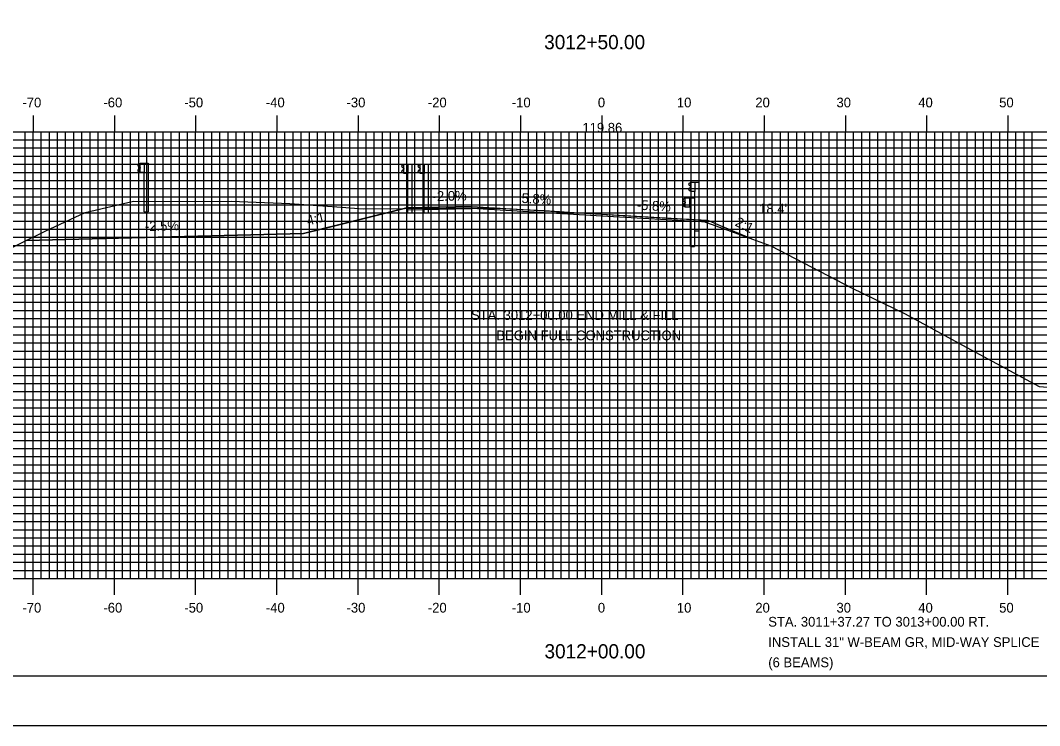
# Model space of a CAD drawing. Extents: x 1684012 to 1684355, y 461260 to 461480.
# Drawn here: x 1684106.1 to 1684231.6, y 461260 to 461346.8 of the extents above; entities that cross this region are included whole.
import ezdxf

# ---------------------------------------------------------------- set-up
doc = ezdxf.new("R2010")
doc.units = 0
for name, color, linetype in [('ANNOTATION', 7, 'Continuous'), ('BORDER', 7, 'Continuous'), ('D_Guardrail_Beam_Rt', 7, 'Continuous'), ('D_Roadway_Centerline', 7, 'Continuous'), ('D_Roadway_Centerline_Text', 7, 'Continuous'), ('D_Roadway_Edge_Shoulder', 7, 'Continuous'), ('D_Roadway_Edge_TW', 7, 'Continuous'), ('D_Roadway_SlopeLines', 7, 'Continuous'), ('D_Text_Standard', 7, 'Continuous'), ('H_V ANNOTATION', 7, 'Continuous'), ('M_Guardrail', 7, 'Continuous'), ('M_Roadway_Centerline', 7, 'Continuous'), ('MAJOR', 7, 'Continuous'), ('MINOR', 7, 'Continuous'), ('PLOT BOUNDARY', 7, 'Continuous'), ('S_Roadway_Centerline', 7, 'Continuous')]:
    doc.layers.add(name, color=color, linetype=linetype)

msp = doc.modelspace()

# ---------------------------------------------------------------- linework, layer by layer
at = {"layer": 'BORDER'}
msp.add_lwpolyline([(1684028.09, 461266.07), (1684348.09, 461266.07), (1684348.09, 461476.07), (1684028.09, 461476.07)], close=True, dxfattribs=at)
at = {"layer": 'D_Guardrail_Beam_Rt'}
for p, q in [((1684187.96, 461324.93), (1684188.65, 461324.93)), ((1684187.96, 461323.77), (1684187.96, 461324.93)), ((1684188.48, 461324.93), (1684188.48, 461323.77)), ((1684188.59, 461324.93), (1684188.59, 461323.77)), ((1684188.65, 461324.93), (1684189.12, 461324.93)), ((1684188.65, 461324.93), (1684188.65, 461323.77)), ((1684189.12, 461324.93), (1684189.12, 461318.93)), ((1684187.87, 461324.83), (1684187.73, 461324.73)), ((1684187.73, 461324.58), (1684187.92, 461324.45)), ((1684187.92, 461324.25), (1684187.73, 461324.11)), ((1684187.73, 461323.97), (1684187.87, 461323.87)), ((1684187.96, 461324.85), (1684187.89, 461324.83)), ((1684187.89, 461323.86), (1684187.96, 461323.85)), ((1684187.96, 461324.38), (1684187.96, 461324.31)), ((1684188.65, 461323.77), (1684187.96, 461323.77)), ((1684188.63, 461318.93), (1684188.63, 461323.77)), ((1684188.63, 461318.93), (1684189.12, 461318.93))]:
    msp.add_line(p, q, dxfattribs=at)
for centre, major_axis, start_param, end_param in [((1684187.78, 461324.66), (-0.0877, 0), 5.323254, 7.243116), ((1684187.78, 461324.04), (-0.0877, 0), 5.323254, 7.243116), ((1684187.89, 461324.79), (-0.0417, 0), 4.907132, 5.323254), ((1684187.89, 461323.9), (-0.0417, 0), 0.959931, 1.376053), ((1684187.88, 461324.38), (0.0789, 0), 0, 0.959931), ((1684187.88, 461324.31), (0.0789, 0), 5.323254, 6.283185)]:
    msp.add_ellipse(centre, major_axis=major_axis, ratio=0.995501, start_param=start_param, end_param=end_param, dxfattribs=at)
at = {"layer": 'D_Roadway_Centerline'}
msp.add_lwpolyline([(1684106.81, 461319.66), (1684140.97, 461320.52), (1684140.99, 461320.52), (1684144.99, 461321.52), (1684144.99, 461321.52), (1684153.68, 461323.7), (1684153.69, 461323.7), (1684161.68, 461323.86), (1684161.69, 461323.86), (1684177.68, 461322.93), (1684177.69, 461322.93), (1684177.7, 461322.93), (1684187.69, 461322.35), (1684190.69, 461322.18), (1684190.69, 461322.17), (1684196.09, 461319.91)], dxfattribs=at)
at = {"layer": 'D_Roadway_Edge_Shoulder'}
for points in [[(1684161.69, 461323.86), (1684153.69, 461323.7), (1684153.69, 461323.45), (1684161.69, 461323.61)], [(1684177.69, 461322.93), (1684187.69, 461322.35), (1684187.69, 461322.35), (1684190.69, 461322.17), (1684190.69, 461321.92), (1684177.69, 461322.68)]]:
    msp.add_lwpolyline(points, close=True, dxfattribs=at)
at = {"layer": 'D_Roadway_Edge_TW'}
msp.add_lwpolyline([(1684161.69, 461323.86), (1684177.69, 461322.93), (1684177.69, 461322.68), (1684161.69, 461323.61)], close=True, dxfattribs=at)
at = {"layer": 'D_Roadway_SlopeLines'}
msp.add_line((1684190.69, 461322.17), (1684196.09, 461319.91), dxfattribs=at)
for points in [[(1684153.69, 461323.7), (1684140.99, 461320.52)], [(1684140.99, 461320.52), (1684106.81, 461319.66)]]:
    msp.add_lwpolyline(points, dxfattribs=at)
at = {"layer": 'M_Guardrail'}
for p, q in [((1684120.76, 461329.11), (1684120.62, 461329.01)), ((1684120.62, 461328.87), (1684120.81, 461328.73)), ((1684120.86, 461329.13), (1684120.78, 461329.12)), ((1684120.85, 461328.66), (1684120.85, 461328.57)), ((1684120.86, 461329.2), (1684121.35, 461329.2)), ((1684120.86, 461328.04), (1684120.86, 461329.2)), ((1684121.35, 461329.2), (1684121.84, 461329.2)), ((1684121.35, 461329.2), (1684121.35, 461328.04)), ((1684121.84, 461329.2), (1684121.84, 461323.2)), ((1684153.24, 461328.99), (1684153.09, 461328.89)), ((1684153.09, 461328.75), (1684153.29, 461328.61)), ((1684153.34, 461329.01), (1684153.25, 461329)), ((1684153.34, 461329.08), (1684153.83, 461329.08)), ((1684153.34, 461327.92), (1684153.34, 461329.08)), ((1684153.83, 461329.08), (1684154.32, 461329.08)), ((1684153.83, 461329.08), (1684153.83, 461327.92)), ((1684154.32, 461329.08), (1684154.32, 461323.08)), ((1684155.24, 461328.99), (1684155.09, 461328.89)), ((1684155.09, 461328.74), (1684155.29, 461328.61)), ((1684155.34, 461329.01), (1684155.26, 461328.99)), ((1684155.34, 461329.08), (1684155.83, 461329.08)), ((1684155.34, 461327.91), (1684155.34, 461329.08)), ((1684155.83, 461329.08), (1684156.32, 461329.08)), ((1684155.83, 461329.08), (1684155.83, 461327.91)), ((1684156.32, 461329.08), (1684156.32, 461323.08)), ((1684120.81, 461328.51), (1684120.62, 461328.37)), ((1684120.62, 461328.23), (1684120.76, 461328.13)), ((1684120.78, 461328.12), (1684120.86, 461328.11)), ((1684121.35, 461328.04), (1684120.86, 461328.04)), ((1684121.35, 461323.2), (1684121.35, 461328.04)), ((1684153.29, 461328.39), (1684153.09, 461328.25)), ((1684153.09, 461328.11), (1684153.24, 461328.01)), ((1684153.25, 461328), (1684153.34, 461327.99)), ((1684153.32, 461328.55), (1684153.32, 461328.45)), ((1684153.83, 461327.92), (1684153.34, 461327.92)), ((1684153.83, 461323.08), (1684153.83, 461327.92)), ((1684155.29, 461328.39), (1684155.09, 461328.25)), ((1684155.09, 461328.11), (1684155.24, 461328.01)), ((1684155.26, 461328), (1684155.34, 461327.99)), ((1684155.32, 461328.54), (1684155.32, 461328.45)), ((1684155.83, 461327.91), (1684155.34, 461327.91)), ((1684155.83, 461323.08), (1684155.83, 461327.91)), ((1684188.56, 461326.79), (1684188.42, 461326.69)), ((1684188.42, 461326.55), (1684188.62, 461326.41)), ((1684188.62, 461326.19), (1684188.42, 461326.05)), ((1684188.66, 461326.81), (1684188.58, 461326.8)), ((1684188.65, 461326.35), (1684188.65, 461326.25)), ((1684188.66, 461326.88), (1684189.15, 461326.88)), ((1684188.66, 461325.72), (1684188.66, 461326.88)), ((1684189.15, 461326.88), (1684189.64, 461326.88)), ((1684189.15, 461326.88), (1684189.15, 461325.72)), ((1684189.64, 461326.88), (1684189.64, 461320.88)), ((1684188.42, 461325.91), (1684188.56, 461325.81)), ((1684188.58, 461325.8), (1684188.66, 461325.79)), ((1684189.15, 461325.72), (1684188.66, 461325.72)), ((1684189.15, 461320.88), (1684189.15, 461325.72)), ((1684121.35, 461323.2), (1684121.84, 461323.2)), ((1684153.83, 461323.08), (1684154.32, 461323.08)), ((1684155.83, 461323.08), (1684156.32, 461323.08)), ((1684189.15, 461320.88), (1684189.64, 461320.88))]:
    msp.add_line(p, q, dxfattribs=at)
for centre, major_axis, start_param, end_param in [((1684120.67, 461328.94), (-0.0877, 0), 5.323254, 7.243116), ((1684120.79, 461329.07), (-0.0417, 0), 4.886922, 5.323254), ((1684120.77, 461328.66), (0.0789, 0), 0, 0.959931), ((1684153.14, 461328.82), (-0.0877, 0), 5.323254, 7.243116), ((1684153.26, 461328.95), (-0.0417, 0), 4.886922, 5.323254), ((1684155.15, 461328.82), (-0.0877, 0), 5.323254, 7.243116), ((1684155.26, 461328.95), (-0.0417, 0), 4.886922, 5.323254), ((1684120.67, 461328.3), (-0.0877, 0), 5.323254, 7.243116), ((1684120.79, 461328.16), (-0.0417, 0), 0.959931, 1.396263), ((1684120.77, 461328.57), (0.0789, 0), 5.323254, 6.283185), ((1684153.14, 461328.18), (-0.0877, 0), 5.323254, 7.243116), ((1684153.26, 461328.04), (-0.0417, 0), 0.959931, 1.396263), ((1684153.24, 461328.55), (0.0789, 0), 0, 0.959931), ((1684153.24, 461328.45), (0.0789, 0), 5.323254, 6.283185), ((1684155.15, 461328.18), (-0.0877, 0), 5.323254, 7.243116), ((1684155.26, 461328.04), (-0.0417, 0), 0.959931, 1.396263), ((1684155.25, 461328.54), (0.0789, 0), 0, 0.959931), ((1684155.25, 461328.45), (0.0789, 0), 5.323254, 6.283185), ((1684188.47, 461326.62), (-0.0877, 0), 5.323254, 7.243116), ((1684188.59, 461326.75), (-0.0417, 0), 4.886922, 5.323254), ((1684188.57, 461326.35), (0.0789, 0), 0, 0.959931), ((1684188.57, 461326.25), (0.0789, 0), 5.323254, 6.283185), ((1684188.47, 461325.98), (-0.0877, 0), 5.323254, 7.243116), ((1684188.59, 461325.84), (-0.0417, 0), 0.959931, 1.396263)]:
    msp.add_ellipse(centre, major_axis=major_axis, ratio=0.995501, start_param=start_param, end_param=end_param, dxfattribs=at)
at = {"layer": 'MAJOR'}
for p, q in [((1684107.69, 461335.08), (1684107.69, 461333.07)), ((1684117.69, 461335.08), (1684117.69, 461333.07)), ((1684127.69, 461335.08), (1684127.69, 461333.07)), ((1684137.69, 461335.08), (1684137.69, 461333.07)), ((1684147.69, 461335.08), (1684147.69, 461333.07)), ((1684157.69, 461335.08), (1684157.69, 461333.07)), ((1684167.69, 461335.08), (1684167.69, 461333.07)), ((1684177.69, 461335.08), (1684177.69, 461333.07)), ((1684187.69, 461335.08), (1684187.69, 461333.07)), ((1684197.69, 461335.08), (1684197.69, 461333.07)), ((1684207.69, 461335.08), (1684207.69, 461333.07)), ((1684217.69, 461335.08), (1684217.69, 461333.07)), ((1684227.69, 461335.08), (1684227.69, 461333.07)), ((1684037.69, 461333.07), (1684317.69, 461333.07)), ((1684037.69, 461333.07), (1684317.69, 461333.07)), ((1684107.69, 461278.07), (1684107.69, 461333.07)), ((1684117.69, 461278.07), (1684117.69, 461333.07)), ((1684127.69, 461278.07), (1684127.69, 461333.07)), ((1684137.69, 461278.07), (1684137.69, 461333.07)), ((1684147.69, 461278.07), (1684147.69, 461333.07)), ((1684157.69, 461278.07), (1684157.69, 461333.07)), ((1684167.69, 461278.07), (1684167.69, 461333.07)), ((1684177.69, 461278.07), (1684177.69, 461333.07)), ((1684187.69, 461278.07), (1684187.69, 461333.07)), ((1684197.69, 461278.07), (1684197.69, 461333.07)), ((1684207.69, 461278.07), (1684207.69, 461333.07)), ((1684217.69, 461278.07), (1684217.69, 461333.07)), ((1684227.69, 461278.07), (1684227.69, 461333.07)), ((1684037.69, 461328.07), (1684317.69, 461328.07)), ((1684037.69, 461323.07), (1684317.69, 461323.07)), ((1684037.69, 461318.07), (1684317.69, 461318.07)), ((1684037.69, 461313.07), (1684317.69, 461313.07)), ((1684037.69, 461308.07), (1684317.69, 461308.07)), ((1684037.69, 461303.07), (1684317.69, 461303.07)), ((1684037.69, 461298.07), (1684317.69, 461298.07)), ((1684037.69, 461293.07), (1684317.69, 461293.07)), ((1684037.69, 461288.07), (1684317.69, 461288.07)), ((1684037.69, 461283.07), (1684317.69, 461283.07)), ((1684037.69, 461278.07), (1684317.69, 461278.07)), ((1684037.69, 461278.07), (1684317.69, 461278.07)), ((1684107.69, 461276.07), (1684107.69, 461278.07)), ((1684117.69, 461276.07), (1684117.69, 461278.07)), ((1684127.69, 461276.07), (1684127.69, 461278.07)), ((1684137.69, 461276.07), (1684137.69, 461278.07)), ((1684147.69, 461276.07), (1684147.69, 461278.07)), ((1684157.69, 461276.07), (1684157.69, 461278.07)), ((1684167.69, 461276.07), (1684167.69, 461278.07)), ((1684177.69, 461276.07), (1684177.69, 461278.07)), ((1684187.69, 461276.07), (1684187.69, 461278.07)), ((1684197.69, 461276.07), (1684197.69, 461278.07)), ((1684207.69, 461276.07), (1684207.69, 461278.07)), ((1684217.69, 461276.07), (1684217.69, 461278.07)), ((1684227.69, 461276.07), (1684227.69, 461278.07))]:
    msp.add_line(p, q, dxfattribs=at)
at = {"layer": 'MINOR'}
for p, q in [((1684106.69, 461278.07), (1684106.69, 461333.07)), ((1684108.69, 461278.07), (1684108.69, 461333.07)), ((1684109.69, 461278.07), (1684109.69, 461333.07)), ((1684110.69, 461278.07), (1684110.69, 461333.07)), ((1684111.69, 461278.07), (1684111.69, 461333.07)), ((1684112.69, 461278.07), (1684112.69, 461333.07)), ((1684113.69, 461278.07), (1684113.69, 461333.07)), ((1684114.69, 461278.07), (1684114.69, 461333.07)), ((1684115.69, 461278.07), (1684115.69, 461333.07)), ((1684116.69, 461278.07), (1684116.69, 461333.07)), ((1684118.69, 461278.07), (1684118.69, 461333.07)), ((1684119.69, 461278.07), (1684119.69, 461333.07)), ((1684120.69, 461278.07), (1684120.69, 461333.07)), ((1684121.69, 461278.07), (1684121.69, 461333.07)), ((1684122.69, 461278.07), (1684122.69, 461333.07)), ((1684123.69, 461278.07), (1684123.69, 461333.07)), ((1684124.69, 461278.07), (1684124.69, 461333.07)), ((1684125.69, 461278.07), (1684125.69, 461333.07)), ((1684126.69, 461278.07), (1684126.69, 461333.07)), ((1684128.69, 461278.07), (1684128.69, 461333.07)), ((1684129.69, 461278.07), (1684129.69, 461333.07)), ((1684130.69, 461278.07), (1684130.69, 461333.07)), ((1684131.69, 461278.07), (1684131.69, 461333.07)), ((1684132.69, 461278.07), (1684132.69, 461333.07)), ((1684133.69, 461278.07), (1684133.69, 461333.07)), ((1684134.69, 461278.07), (1684134.69, 461333.07)), ((1684135.69, 461278.07), (1684135.69, 461333.07)), ((1684136.69, 461278.07), (1684136.69, 461333.07)), ((1684138.69, 461278.07), (1684138.69, 461333.07)), ((1684139.69, 461278.07), (1684139.69, 461333.07)), ((1684140.69, 461278.07), (1684140.69, 461333.07)), ((1684141.69, 461278.07), (1684141.69, 461333.07)), ((1684142.69, 461278.07), (1684142.69, 461333.07)), ((1684143.69, 461278.07), (1684143.69, 461333.07)), ((1684144.69, 461278.07), (1684144.69, 461333.07)), ((1684145.69, 461278.07), (1684145.69, 461333.07)), ((1684146.69, 461278.07), (1684146.69, 461333.07)), ((1684148.69, 461278.07), (1684148.69, 461333.07)), ((1684149.69, 461278.07), (1684149.69, 461333.07)), ((1684150.69, 461278.07), (1684150.69, 461333.07)), ((1684151.69, 461278.07), (1684151.69, 461333.07)), ((1684152.69, 461278.07), (1684152.69, 461333.07)), ((1684153.69, 461278.07), (1684153.69, 461333.07)), ((1684154.69, 461278.07), (1684154.69, 461333.07)), ((1684155.69, 461278.07), (1684155.69, 461333.07)), ((1684156.69, 461278.07), (1684156.69, 461333.07)), ((1684158.69, 461278.07), (1684158.69, 461333.07)), ((1684159.69, 461278.07), (1684159.69, 461333.07)), ((1684160.69, 461278.07), (1684160.69, 461333.07)), ((1684161.69, 461278.07), (1684161.69, 461333.07)), ((1684162.69, 461278.07), (1684162.69, 461333.07)), ((1684163.69, 461278.07), (1684163.69, 461333.07)), ((1684164.69, 461278.07), (1684164.69, 461333.07)), ((1684165.69, 461278.07), (1684165.69, 461333.07)), ((1684166.69, 461278.07), (1684166.69, 461333.07)), ((1684168.69, 461278.07), (1684168.69, 461333.07)), ((1684169.69, 461278.07), (1684169.69, 461333.07)), ((1684170.69, 461278.07), (1684170.69, 461333.07)), ((1684171.69, 461278.07), (1684171.69, 461333.07)), ((1684172.69, 461278.07), (1684172.69, 461333.07)), ((1684173.69, 461278.07), (1684173.69, 461333.07)), ((1684174.69, 461278.07), (1684174.69, 461333.07)), ((1684175.69, 461278.07), (1684175.69, 461333.07)), ((1684176.69, 461278.07), (1684176.69, 461333.07)), ((1684178.69, 461278.07), (1684178.69, 461333.07)), ((1684179.69, 461278.07), (1684179.69, 461333.07)), ((1684180.69, 461278.07), (1684180.69, 461333.07)), ((1684181.69, 461278.07), (1684181.69, 461333.07)), ((1684182.69, 461278.07), (1684182.69, 461333.07)), ((1684183.69, 461278.07), (1684183.69, 461333.07)), ((1684184.69, 461278.07), (1684184.69, 461333.07)), ((1684185.69, 461278.07), (1684185.69, 461333.07)), ((1684186.69, 461278.07), (1684186.69, 461333.07)), ((1684188.69, 461278.07), (1684188.69, 461333.07)), ((1684189.69, 461278.07), (1684189.69, 461333.07)), ((1684190.69, 461278.07), (1684190.69, 461333.07)), ((1684191.69, 461278.07), (1684191.69, 461333.07)), ((1684192.69, 461278.07), (1684192.69, 461333.07)), ((1684193.69, 461278.07), (1684193.69, 461333.07)), ((1684194.69, 461278.07), (1684194.69, 461333.07)), ((1684195.69, 461278.07), (1684195.69, 461333.07)), ((1684196.69, 461278.07), (1684196.69, 461333.07)), ((1684198.69, 461278.07), (1684198.69, 461333.07)), ((1684199.69, 461278.07), (1684199.69, 461333.07)), ((1684200.69, 461278.07), (1684200.69, 461333.07)), ((1684201.69, 461278.07), (1684201.69, 461333.07)), ((1684202.69, 461278.07), (1684202.69, 461333.07)), ((1684203.69, 461278.07), (1684203.69, 461333.07)), ((1684204.69, 461278.07), (1684204.69, 461333.07)), ((1684205.69, 461278.07), (1684205.69, 461333.07)), ((1684206.69, 461278.07), (1684206.69, 461333.07)), ((1684208.69, 461278.07), (1684208.69, 461333.07)), ((1684209.69, 461278.07), (1684209.69, 461333.07)), ((1684210.69, 461278.07), (1684210.69, 461333.07)), ((1684211.69, 461278.07), (1684211.69, 461333.07)), ((1684212.69, 461278.07), (1684212.69, 461333.07)), ((1684213.69, 461278.07), (1684213.69, 461333.07)), ((1684214.69, 461278.07), (1684214.69, 461333.07)), ((1684215.69, 461278.07), (1684215.69, 461333.07)), ((1684216.69, 461278.07), (1684216.69, 461333.07)), ((1684218.69, 461278.07), (1684218.69, 461333.07)), ((1684219.69, 461278.07), (1684219.69, 461333.07)), ((1684220.69, 461278.07), (1684220.69, 461333.07)), ((1684221.69, 461278.07), (1684221.69, 461333.07)), ((1684222.69, 461278.07), (1684222.69, 461333.07)), ((1684223.69, 461278.07), (1684223.69, 461333.07)), ((1684224.69, 461278.07), (1684224.69, 461333.07)), ((1684225.69, 461278.07), (1684225.69, 461333.07)), ((1684226.69, 461278.07), (1684226.69, 461333.07)), ((1684228.69, 461278.07), (1684228.69, 461333.07)), ((1684229.69, 461278.07), (1684229.69, 461333.07)), ((1684230.69, 461278.07), (1684230.69, 461333.07)), ((1684037.69, 461332.07), (1684317.69, 461332.07)), ((1684037.69, 461331.07), (1684317.69, 461331.07)), ((1684037.69, 461330.07), (1684317.69, 461330.07)), ((1684037.69, 461329.07), (1684317.69, 461329.07)), ((1684037.69, 461327.07), (1684317.69, 461327.07)), ((1684037.69, 461326.07), (1684317.69, 461326.07)), ((1684037.69, 461325.07), (1684317.69, 461325.07)), ((1684037.69, 461324.07), (1684317.69, 461324.07)), ((1684037.69, 461322.07), (1684317.69, 461322.07)), ((1684037.69, 461321.07), (1684317.69, 461321.07)), ((1684037.69, 461320.07), (1684317.69, 461320.07)), ((1684037.69, 461319.07), (1684317.69, 461319.07)), ((1684037.69, 461317.07), (1684317.69, 461317.07)), ((1684037.69, 461316.07), (1684317.69, 461316.07)), ((1684037.69, 461315.07), (1684317.69, 461315.07)), ((1684037.69, 461314.07), (1684317.69, 461314.07)), ((1684037.69, 461312.07), (1684317.69, 461312.07)), ((1684037.69, 461311.07), (1684317.69, 461311.07)), ((1684037.69, 461310.07), (1684317.69, 461310.07)), ((1684037.69, 461309.07), (1684317.69, 461309.07)), ((1684037.69, 461307.07), (1684317.69, 461307.07)), ((1684037.69, 461306.07), (1684317.69, 461306.07)), ((1684037.69, 461305.07), (1684317.69, 461305.07)), ((1684037.69, 461304.07), (1684317.69, 461304.07)), ((1684037.69, 461302.07), (1684317.69, 461302.07)), ((1684037.69, 461301.07), (1684317.69, 461301.07)), ((1684037.69, 461300.07), (1684317.69, 461300.07)), ((1684037.69, 461299.07), (1684317.69, 461299.07)), ((1684037.69, 461297.07), (1684317.69, 461297.07)), ((1684037.69, 461296.07), (1684317.69, 461296.07)), ((1684037.69, 461295.07), (1684317.69, 461295.07)), ((1684037.69, 461294.07), (1684317.69, 461294.07)), ((1684037.69, 461292.07), (1684317.69, 461292.07)), ((1684037.69, 461291.07), (1684317.69, 461291.07)), ((1684037.69, 461290.07), (1684317.69, 461290.07)), ((1684037.69, 461289.07), (1684317.69, 461289.07)), ((1684037.69, 461287.07), (1684317.69, 461287.07)), ((1684037.69, 461286.07), (1684317.69, 461286.07)), ((1684037.69, 461285.07), (1684317.69, 461285.07)), ((1684037.69, 461284.07), (1684317.69, 461284.07)), ((1684037.69, 461282.07), (1684317.69, 461282.07)), ((1684037.69, 461281.07), (1684317.69, 461281.07)), ((1684037.69, 461280.07), (1684317.69, 461280.07)), ((1684037.69, 461279.07), (1684317.69, 461279.07))]:
    msp.add_line(p, q, dxfattribs=at)
at = {"layer": 'PLOT BOUNDARY'}
msp.add_lwpolyline([(1684011.9, 461259.95), (1684351.9, 461259.95), (1684351.9, 461479.95), (1684011.9, 461479.95)], close=True, dxfattribs=at)
at = {"layer": 'S_Roadway_Centerline'}
msp.add_lwpolyline([(1684097.62, 461315.16), (1684109.16, 461320.82), (1684114.09, 461323.14), (1684119.34, 461324.36), (1684120.04, 461324.51), (1684121.57, 461324.5), (1684132.07, 461324.52), (1684134.11, 461324.43), (1684139.27, 461324.25), (1684145.63, 461323.77), (1684148.31, 461323.58), (1684158.53, 461323.64), (1684164.69, 461323.67), (1684168.01, 461323.5), (1684170.65, 461323.37), (1684174.91, 461323.1), (1684180.99, 461322.72), (1684186.54, 461322.39), (1684189.7, 461322.21), (1684192.65, 461321.15), (1684198.5, 461319.04), (1684208.5, 461313.83), (1684215.04, 461310.65), (1684222.09, 461306.78), (1684231.55, 461301.69), (1684238.06, 461301.23)], dxfattribs=at)

# ---------------------------------------------------------------- texts
at = {"layer": 'ANNOTATION'}
for s, rotation, p in [('-2.0%', 1.1457, (1684156.88, 461324.53)), ('5.8%', 356.6806, (1684167.79, 461324.31)), ('-5.8%', 356.6806, (1684181.98, 461323.48)), ('4:1', 14.0362, (1684141.53, 461321.52)), ('2:1', 333.4349, (1684194.01, 461321.55)), ('-2.5%', 1.4415, (1684121.46, 461320.83))]:
    msp.add_text(s, height=1.2, rotation=rotation, dxfattribs=at).set_placement(p)
at = {"layer": 'D_Roadway_Centerline_Text'}
msp.add_text('119.86', height=1.2, dxfattribs=at).set_placement((1684175.31, 461332.96))
at = {"layer": 'D_Text_Standard'}
for s, p in [("18.4'", (1684197.07, 461323)), ('STA. 3012+00.00 END MILL & FILL', (1684161.59, 461309.9)), ('BEGIN FULL CONSTRUCTION', (1684164.72, 461307.4)), ('STA. 3011+37.27 TO 3013+00.00 RT.', (1684198.19, 461272.14)), ('INSTALL 31" W-BEAM GR, MID-WAY SPLICE', (1684198.19, 461269.64)), ('(6 BEAMS)', (1684198.19, 461267.14))]:
    msp.add_text(s, height=1.2, dxfattribs=at).set_placement(p)
at = {"layer": 'H_V ANNOTATION'}
for s, height, p in [('3012+50.00', 1.75, (1684170.6, 461343.23)), ('-70', 1.2, (1684106.37, 461336.07)), ('-60', 1.2, (1684116.34, 461336.07)), ('-50', 1.2, (1684126.3, 461336.07)), ('-40', 1.2, (1684136.34, 461336.07)), ('-30', 1.2, (1684146.27, 461336.07)), ('-20', 1.2, (1684156.28, 461336.07)), ('-10', 1.2, (1684166.62, 461336.07)), ('0', 1.2, (1684177.21, 461336.07)), ('10', 1.2, (1684186.94, 461336.07)), ('20', 1.2, (1684196.6, 461336.07)), ('30', 1.2, (1684206.59, 461336.07)), ('40', 1.2, (1684216.66, 461336.07)), ('50', 1.2, (1684226.62, 461336.07)), ('-70', 1.2, (1684106.37, 461273.87)), ('-60', 1.2, (1684116.34, 461273.87)), ('-50', 1.2, (1684126.3, 461273.87)), ('-40', 1.2, (1684136.34, 461273.87)), ('-30', 1.2, (1684146.27, 461273.87)), ('-20', 1.2, (1684156.28, 461273.87)), ('-10', 1.2, (1684166.62, 461273.87)), ('0', 1.2, (1684177.21, 461273.87)), ('10', 1.2, (1684186.94, 461273.87)), ('20', 1.2, (1684196.6, 461273.87)), ('30', 1.2, (1684206.59, 461273.87)), ('40', 1.2, (1684216.66, 461273.87)), ('50', 1.2, (1684226.62, 461273.87)), ('3012+00.00', 1.75, (1684170.64, 461268.23))]:
    msp.add_text(s, height=height, dxfattribs=at).set_placement(p)
at = {"layer": 'M_Roadway_Centerline'}
for s, p in [('C', (1684139.26, 461324.25)), ('L', (1684139.27, 461324.25)), ('C', (1684170.65, 461323.37)), ('L', (1684170.65, 461323.36))]:
    msp.add_text(s, height=0.0146, dxfattribs=at).set_placement(p)

doc.saveas('drawing.dxf')
